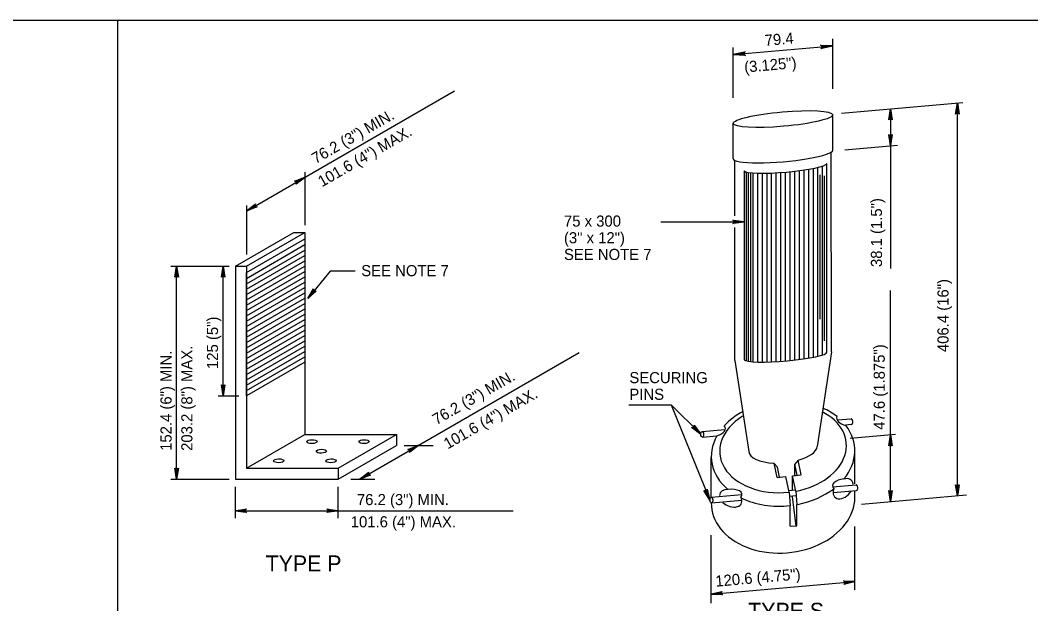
# Model space of a CAD drawing. Extents: x 640253 to 641999, y 298458 to 299646.
# Drawn here: x 640526.1 to 640798.8, y 298630.1 to 298787.7 of the extents above; entities that cross this region are included whole.
import ezdxf

# ---------------------------------------------------------------- set-up
doc = ezdxf.new("R2010")
doc.units = 0
doc.layers.add('1', color=7, linetype='Continuous')
doc.layers.add('2', color=7, linetype='Continuous')

msp = doc.modelspace()

# ---------------------------------------------------------------- linework, layer by layer
at = {"layer": '1'}
for p, q in [((640293.31, 298787.67), (641079.31, 298787.67)), ((640552.4, 298501.97), (640552.4, 298787.67))]:
    msp.add_line(p, q, dxfattribs=at)
at = {"layer": '2'}
for p, q in [((640745.35, 298769.11), (640745.35, 298782.64)), ((640718.51, 298778.37), (640745.35, 298780.72)), ((640718.51, 298766.76), (640718.51, 298780.28)), ((640587.19, 298736.22), (640643.29, 298768.61)), ((640747.71, 298762.61), (640780.48, 298765.48)), ((640778.98, 298659.27), (640778.98, 298765.33)), ((640760.93, 298763.77), (640760.93, 298753.8)), ((640745.35, 298752.61), (640745.35, 298762.15)), ((640718.51, 298750.3), (640718.51, 298759.84)), ((640744.97, 298698.11), (640744.96, 298752.08)), ((640748.58, 298752.71), (640762.8, 298753.96)), ((640760.93, 298753.8), (640760.93, 298720.65)), ((640718.9, 298734.89), (640718.9, 298749.84)), ((640743.77, 298698.07), (640743.76, 298748.98)), ((640602.93, 298732.38), (640602.93, 298746.61)), ((640721.41, 298746.98), (640721.41, 298696)), ((640721.41, 298746.59), (640721.63, 298746.81)), ((640722.06, 298695.59), (640722.06, 298746.56)), ((640722.61, 298695.59), (640722.61, 298746.55)), ((640723.24, 298695.59), (640723.24, 298746.56)), ((640723.86, 298695.45), (640723.86, 298746.43)), ((640725.11, 298695.4), (640725.11, 298746.37)), ((640726.36, 298695.39), (640726.36, 298746.36)), ((640727.61, 298695.4), (640727.61, 298746.38)), ((640728.86, 298695.45), (640728.86, 298746.42)), ((640730.11, 298695.51), (640730.11, 298746.48)), ((640731.36, 298695.59), (640731.36, 298746.57)), ((640732.61, 298695.69), (640732.61, 298746.66)), ((640733.86, 298695.81), (640733.86, 298746.78)), ((640735.11, 298695.94), (640735.11, 298746.91)), ((640736.36, 298696.1), (640736.36, 298747.07)), ((640737.61, 298696.27), (640737.61, 298747.24)), ((640738.86, 298696.47), (640738.86, 298747.44)), ((640740.11, 298696.7), (640740.11, 298747.67)), ((640741.36, 298696.98), (640741.36, 298747.95)), ((640742.61, 298697.33), (640742.61, 298748.3)), ((640743.76, 298748.51), (640743.55, 298748.73)), ((640741.93, 298706.99), (640741.93, 298745.92)), ((640743.12, 298701.13), (640743.12, 298745.69)), ((640587.19, 298724.38), (640587.19, 298737.68)), ((640698.95, 298733.24), (640721.41, 298733.24)), ((640584.12, 298721.28), (640599.86, 298730.37)), ((640587.12, 298721.28), (640602.86, 298730.37)), ((640599.86, 298730.37), (640602.86, 298730.37)), ((640602.86, 298730.37), (640602.86, 298675.87)), ((640718.91, 298695.83), (640718.9, 298731.67)), ((640587.12, 298717.99), (640602.86, 298727.08)), ((640587.12, 298716.54), (640602.86, 298725.63)), ((640587.12, 298715.1), (640602.86, 298724.19)), ((640587.12, 298713.66), (640602.86, 298722.75)), ((640566.74, 298721.28), (640582.49, 298721.28)), ((640568.28, 298663.78), (640568.28, 298721.28)), ((640580.82, 298686.28), (640580.82, 298721.28)), ((640584.12, 298721.28), (640587.12, 298721.28)), ((640584.12, 298721.28), (640584.12, 298663.78)), ((640587.12, 298712.21), (640602.86, 298721.3)), ((640587.12, 298721.28), (640587.12, 298666.78)), ((640587.12, 298710.77), (640602.86, 298719.86)), ((640587.12, 298719.28), (640587.35, 298719.68)), ((640587.12, 298719.32), (640587.32, 298719.66)), ((640609.71, 298719.96), (640603.7, 298712.54)), ((640616.48, 298719.96), (640609.71, 298719.96)), ((640587.12, 298709.33), (640602.86, 298718.41)), ((640587.12, 298707.88), (640602.86, 298716.97)), ((640587.12, 298706.44), (640602.86, 298715.53)), ((640587.12, 298705), (640602.86, 298714.09)), ((640760.93, 298657.71), (640760.93, 298714.7)), ((640587.12, 298703.55), (640602.86, 298712.64)), ((640587.12, 298702.11), (640602.86, 298711.2)), ((640587.12, 298700.67), (640602.86, 298709.75)), ((640587.12, 298699.22), (640602.86, 298708.31)), ((640587.12, 298697.78), (640602.86, 298706.87)), ((640587.12, 298696.34), (640602.86, 298705.43)), ((640587.12, 298694.89), (640602.86, 298703.98)), ((640587.12, 298693.45), (640602.86, 298702.54)), ((640587.12, 298692.01), (640602.86, 298701.09)), ((640587.12, 298690.56), (640602.86, 298699.65)), ((640587.12, 298689.12), (640602.86, 298698.21)), ((640617.72, 298663.78), (640676.89, 298697.94)), ((640744.97, 298698.11), (640741.18, 298672.58)), ((640587.12, 298687.68), (640602.86, 298696.76)), ((640718.91, 298695.83), (640722.69, 298671.24)), ((640579.47, 298686.28), (640585.04, 298686.28)), ((640690.3, 298683.85), (640701.76, 298683.85)), ((640701.76, 298683.85), (640709.73, 298675.91)), ((640701.76, 298683.85), (640712.18, 298658.13)), ((640746.61, 298679.77), (640750.3, 298680.09)), ((640748.75, 298678.44), (640750.42, 298678.58)), ((640587.12, 298666.78), (640602.86, 298675.87)), ((640602.86, 298675.87), (640627.58, 298675.87)), ((640611.84, 298666.78), (640627.58, 298675.87)), ((640627.58, 298675.87), (640627.58, 298672.87)), ((640710.07, 298676.65), (640716.25, 298677.17)), ((640710.18, 298675.14), (640714.07, 298675.47)), ((640750.09, 298674.81), (640762.33, 298675.88)), ((640611.84, 298663.78), (640627.58, 298672.87)), ((640629.69, 298672.87), (640637.47, 298672.87)), ((640751.32, 298662.52), (640751.32, 298671.49)), ((640712.57, 298658.9), (640712.57, 298669.6)), ((640730.36, 298664.26), (640729.56, 298668.13)), ((640729.58, 298668.02), (640730.45, 298667.02)), ((640736.01, 298668.88), (640735.1, 298667.79)), ((640735.1, 298664.75), (640735.1, 298667.79)), ((640735.72, 298664.82), (640735.1, 298667.79)), ((640736.83, 298664.91), (640736, 298668.9)), ((640587.12, 298666.78), (640611.84, 298666.78)), ((640611.84, 298666.78), (640611.84, 298663.78)), ((640730.36, 298664.26), (640732.68, 298664.47)), ((640731.01, 298664.3), (640730.45, 298667.02)), ((640733.56, 298660.25), (640732.68, 298664.47)), ((640734.51, 298664.7), (640736.83, 298664.91)), ((640735.37, 298660.56), (640734.51, 298664.7)), ((640734.51, 298660.92), (640734.51, 298664.7)), ((640566.74, 298663.78), (640582.49, 298663.78)), ((640584.12, 298663.78), (640611.84, 298663.78)), ((640584.12, 298653.23), (640584.12, 298661.74)), ((640611.84, 298653.23), (640611.84, 298661.74)), ((640615.31, 298663.78), (640621.72, 298663.78)), ((640745.28, 298661.72), (640751.64, 298662.26)), ((640712.51, 298658.91), (640720.85, 298659.63)), ((640733.46, 298660.71), (640735.31, 298660.86)), ((640733.56, 298660.25), (640733.88, 298656.62)), ((640733.65, 298659.21), (640735.48, 298659.36)), ((640735.5, 298651.22), (640734.51, 298659.03)), ((640735.37, 298660.56), (640735.7, 298656.93)), ((640745.44, 298660.21), (640751.77, 298660.75)), ((640751.32, 298658.55), (640751.32, 298660.75)), ((640753.15, 298657.03), (640781.49, 298659.51)), ((640712.63, 298657.41), (640720.84, 298658.11)), ((640733.88, 298651.05), (640733.88, 298656.62)), ((640735.7, 298651.21), (640735.7, 298656.93)), ((640584.12, 298655.27), (640659.11, 298655.27)), ((640733.88, 298651.05), (640735.7, 298651.21)), ((640751.32, 298633.93), (640751.32, 298651.02)), ((640712.57, 298630.28), (640712.57, 298648.65)), ((640712.57, 298632.73), (640751.32, 298636.12))]:
    msp.add_line(p, q, dxfattribs=at)
for points in [[(640721.62, 298778.25), (640721.48, 298778.47), (640718.51, 298778.37), (640721.62, 298778.25), (640721.78, 298778.13), (640718.51, 298778.37), (640721.45, 298778.78), (640721.54, 298779.01), (640718.51, 298778.37), (640721.69, 298779.17), (640721.54, 298779.01)], [(640721.62, 298778.25), (640721.48, 298778.47), (640718.51, 298778.37), (640721.62, 298778.25), (640721.78, 298778.13), (640718.51, 298778.37), (640721.45, 298778.78), (640721.54, 298779.01), (640718.51, 298778.37), (640721.69, 298779.17), (640721.54, 298779.01)], [(640742.24, 298780.84), (640742.38, 298780.63), (640745.35, 298780.72), (640742.24, 298780.84), (640742.07, 298780.96), (640745.35, 298780.72), (640742.41, 298780.32), (640742.32, 298780.09), (640745.35, 298780.72), (640742.17, 298779.92), (640742.32, 298780.09)], [(640778.62, 298762.47), (640778.83, 298762.58), (640778.98, 298765.33), (640778.62, 298762.47), (640778.5, 298762.33), (640778.98, 298765.33), (640779.12, 298762.58), (640779.32, 298762.48), (640778.98, 298765.33), (640779.46, 298762.33), (640779.32, 298762.48)], [(640760.57, 298760.91), (640760.78, 298761.02), (640760.93, 298763.77), (640760.57, 298760.91), (640760.45, 298760.77), (640760.93, 298763.77), (640761.06, 298761.02), (640761.27, 298760.92), (640760.93, 298763.77), (640761.41, 298760.77), (640761.27, 298760.92)], [(640761.29, 298756.65), (640761.08, 298756.54), (640760.93, 298753.8), (640761.29, 298756.65), (640761.41, 298756.8), (640760.93, 298753.8), (640760.79, 298756.54), (640760.59, 298756.64), (640760.93, 298753.8), (640760.45, 298756.8), (640760.59, 298756.64)], [(640600.28, 298744.19), (640600.48, 298744.07), (640602.93, 298745.31), (640600.28, 298744.19), (640600.09, 298744.23), (640602.93, 298745.31), (640600.62, 298743.82), (640600.64, 298743.59), (640602.93, 298745.31), (640600.57, 298743.39), (640600.64, 298743.59)], [(640589.84, 298737.33), (640589.64, 298737.46), (640587.19, 298736.22), (640589.84, 298737.33), (640590.03, 298737.3), (640587.19, 298736.22), (640589.5, 298737.71), (640589.48, 298737.93), (640587.19, 298736.22), (640589.55, 298738.13), (640589.48, 298737.93)], [(640718.56, 298733.6), (640718.66, 298733.39), (640721.41, 298733.24), (640718.56, 298733.6), (640718.41, 298733.72), (640721.41, 298733.24), (640718.66, 298733.11), (640718.56, 298732.9), (640721.41, 298733.24), (640718.41, 298732.76), (640718.56, 298732.9)], [(640567.92, 298718.43), (640568.13, 298718.53), (640568.28, 298721.28), (640567.92, 298718.43), (640567.8, 298718.28), (640568.28, 298721.28), (640568.42, 298718.53), (640568.62, 298718.43), (640568.28, 298721.28), (640568.76, 298718.28), (640568.62, 298718.43)], [(640580.46, 298718.43), (640580.67, 298718.53), (640580.82, 298721.28), (640580.46, 298718.43), (640580.34, 298718.28), (640580.82, 298721.28), (640580.96, 298718.53), (640581.16, 298718.43), (640580.82, 298721.28), (640581.3, 298718.28), (640581.16, 298718.43)], [(640605.78, 298714.53), (640605.55, 298714.58), (640603.7, 298712.54), (640605.78, 298714.53), (640605.97, 298714.56), (640603.7, 298712.54), (640605.33, 298714.75), (640605.23, 298714.96), (640603.7, 298712.54), (640605.22, 298715.17), (640605.23, 298714.96)], [(640581.18, 298689.13), (640580.97, 298689.03), (640580.82, 298686.28), (640581.18, 298689.13), (640581.3, 298689.28), (640580.82, 298686.28), (640580.69, 298689.03), (640580.48, 298689.13), (640580.82, 298686.28), (640580.34, 298689.28), (640580.48, 298689.13)], [(640707.95, 298678.17), (640707.88, 298677.95), (640709.73, 298675.91), (640707.95, 298678.17), (640707.93, 298678.36), (640709.73, 298675.91), (640707.68, 298677.74), (640707.47, 298677.67), (640709.73, 298675.91), (640707.26, 298677.68), (640707.47, 298677.67)], [(640760.57, 298672.9), (640760.78, 298673.01), (640760.93, 298675.75), (640760.57, 298672.9), (640760.45, 298672.75), (640760.93, 298675.75), (640761.06, 298673.01), (640761.27, 298672.91), (640760.93, 298675.75), (640761.41, 298672.75), (640761.27, 298672.91)], [(640630.82, 298671.76), (640631.02, 298671.63), (640633.47, 298672.87), (640630.82, 298671.76), (640630.63, 298671.79), (640633.47, 298672.87), (640631.16, 298671.38), (640631.18, 298671.16), (640633.47, 298672.87), (640631.11, 298670.96), (640631.18, 298671.16)], [(640568.64, 298666.63), (640568.43, 298666.53), (640568.28, 298663.78), (640568.64, 298666.63), (640568.76, 298666.78), (640568.28, 298663.78), (640568.14, 298666.53), (640567.94, 298666.63), (640568.28, 298663.78), (640567.8, 298666.78), (640567.94, 298666.63)], [(640620.37, 298664.9), (640620.18, 298665.02), (640617.72, 298663.78), (640620.37, 298664.9), (640620.56, 298664.86), (640617.72, 298663.78), (640620.03, 298665.27), (640620.02, 298665.5), (640617.72, 298663.78), (640620.08, 298665.69), (640620.02, 298665.5)], [(640779.34, 298662.13), (640779.13, 298662.02), (640778.98, 298659.27), (640779.34, 298662.13), (640779.46, 298662.27), (640778.98, 298659.27), (640778.85, 298662.02), (640778.64, 298662.12), (640778.98, 298659.27), (640778.5, 298662.27), (640778.64, 298662.12)], [(640711.42, 298660.91), (640711.27, 298660.73), (640712.18, 298658.13), (640711.42, 298660.91), (640711.48, 298661.09), (640712.18, 298658.13), (640711.01, 298660.62), (640710.78, 298660.64), (640712.18, 298658.13), (640710.59, 298660.73), (640710.78, 298660.64)], [(640761.29, 298660.57), (640761.08, 298660.46), (640760.93, 298657.71), (640761.29, 298660.57), (640761.41, 298660.71), (640760.93, 298657.71), (640760.79, 298660.46), (640760.59, 298660.56), (640760.93, 298657.71), (640760.45, 298660.71), (640760.59, 298660.56)], [(640586.97, 298654.91), (640586.87, 298655.12), (640584.12, 298655.27), (640586.97, 298654.91), (640587.12, 298654.79), (640584.12, 298655.27), (640586.87, 298655.41), (640586.97, 298655.61), (640584.12, 298655.27), (640587.12, 298655.75), (640586.97, 298655.61)], [(640608.98, 298655.63), (640609.09, 298655.42), (640611.84, 298655.27), (640608.98, 298655.63), (640608.84, 298655.75), (640611.84, 298655.27), (640609.09, 298655.14), (640608.99, 298654.93), (640611.84, 298655.27), (640608.84, 298654.79), (640608.99, 298654.93)], [(640748.44, 298636.23), (640748.57, 298636.03), (640751.32, 298636.12), (640748.44, 298636.23), (640748.29, 298636.34), (640751.32, 298636.12), (640748.6, 298635.75), (640748.51, 298635.53), (640751.32, 298636.12), (640748.37, 298635.38), (640748.51, 298635.53)], [(640715.45, 298632.62), (640715.32, 298632.82), (640712.57, 298632.73), (640715.45, 298632.62), (640715.6, 298632.51), (640712.57, 298632.73), (640715.29, 298633.1), (640715.37, 298633.32), (640712.57, 298632.73), (640715.52, 298633.47), (640715.37, 298633.32)]]:
    msp.add_lwpolyline(points, dxfattribs=at)
msp.add_lwpolyline([(640587.12, 298686.28), (640587.12, 298719.55), (640602.86, 298728.64), (640602.86, 298695.37)], close=True, dxfattribs=at)
for centre, major_axis, ratio in [((640731.93, 298760.98), (13.42, 1.17), 0.145281), ((640710.12, 298675.89), (0.064, -0.752), 0.512732), ((640604.79, 298673.91), (1.39, 0.03), 0.379302), ((640618.87, 298673.91), (1.39, 0.03), 0.379302), ((640607.35, 298671.32), (1.39, 0.03), 0.379302), ((640595.82, 298668.73), (1.39, 0.03), 0.379302), ((640609.91, 298668.73), (1.39, 0.03), 0.379302), ((640712.57, 298658.16), (0.064, -0.752), 0.512732)]:
    msp.add_ellipse(centre, major_axis=major_axis, ratio=ratio, dxfattribs=at)
for centre, major_axis, ratio, start_param, end_param in [((640731.93, 298751.43), (13.42, 1.17), 0.145281, 3.11632, 6.285895), ((640732.57, 298748.05), (11.2, 0.98), 0.122972, 3.210002, 6.25293), ((640732.58, 298697.08), (11.2, 0.98), 0.122972, 3.210002, 6.291685), ((640731.94, 298672.08), (17.07, 1.49), 0.694967, 2.202733, 4.738504), ((640731.94, 298670.7), (19.33, 1.69), 0.73071, 2.097917, 2.468804), ((640731.94, 298672.08), (17.07, 1.49), 0.694967, 4.864246, 7.131508), ((640731.94, 298670.7), (19.33, 1.69), 0.73071, 0.656059, 0.918196), ((640712.01, 298677.2), (-4.38, -0.28), 0.475219, 2.036448, 3.493745), ((640750.78, 298680.04), (4.38, -0.28), 0.475219, 2.977963, 4.296796), ((640731.94, 298670.7), (19.33, 1.69), 0.73071, 5.661526, 6.723992), ((640750.36, 298679.33), (0.064, -0.752), 0.512732, 0.00107, 3.141593), ((640731.94, 298670.7), (19.33, 1.69), 0.73071, 2.680187, 3.772289), ((640732.14, 298672.12), (9.04, 0.79), 0.424128, 5.116194, 6.19738), ((640731.73, 298672.03), (9.04, 0.79), 0.424128, 3.141593, 4.432781), ((640748.9, 298662.15), (3.65, 0.24), 0.475219, 1.675831, 3.574843), ((640748.15, 298661.2), (2.24, 2.27), 0.672987, 5.779184, 7.175378), ((640751.7, 298661.51), (0.064, -0.752), 0.512732, 0.00107, 3.141593), ((640717.83, 298658.61), (2.87, -1.38), 0.672987, 2.130551, 3.418187), ((640717.83, 298658.61), (2.87, -1.38), 0.672987, 4.245803, 7.059428), ((640717.22, 298659.25), (-3.62, -0.53), 0.475219, 2.692089, 4.679207), ((640731.94, 298670.7), (19.33, 1.69), 0.73071, 4.853626, 5.433989), ((640748.15, 298661.2), (2.24, 2.27), 0.672987, 2.176573, 5.044432), ((640731.94, 298658.04), (19.33, 1.69), 0.73071, 3.065603, 6.219513), ((640731.94, 298670.7), (19.33, 1.69), 0.73071, 4.023734, 4.749104)]:
    msp.add_ellipse(centre, major_axis=major_axis, ratio=ratio, start_param=start_param, end_param=end_param, dxfattribs=at)

# ---------------------------------------------------------------- texts
for s, rotation, p in [('79.4', 5.0068, (640727.12, 298780.7)), ('(3.125")', 5.0068, (640721.59, 298773.52)), ('76.2 (3") MIN.', 30, (640605.81, 298748.79)), ('101.6 (4") MAX.', 30, (640607.5, 298742.55)), ('38.1 (1.5")', 90, (640758.64, 298721.04)), ('406.4 (16")', 90, (640776.61, 298698.08)), ('125 (5")', 90, (640579.45, 298693.52)), ('47.6 (1.875")', 90, (640759.4, 298677.12)), ('152.4 (6") MIN.', 90, (640566.91, 298671.41)), ('203.2 (8") MAX.', 90, (640572.53, 298671.41)), ('76.2 (3") MIN.', 30, (640638.4, 298678.32)), ('101.6 (4") MAX.', 30, (640641.43, 298671.78)), ('120.6 (4.75")', 5.0052, (640713.8, 298634.73))]:
    msp.add_text(s, height=3, rotation=rotation, dxfattribs=at).set_placement(p)
for s, height, p in [('75 x 300', 3, (640672.81, 298731.95)), ('(3" x 12")', 3, (640672.81, 298727.45)), ('SEE NOTE 7', 3, (640672.81, 298722.95)), ('SEE NOTE 7', 3, (640618.1, 298718.57)), ('SECURING', 3, (640690.46, 298689.69)), ('PINS', 3, (640690.46, 298685.19)), ('76.2 (3") MIN.', 3, (640616.93, 298656.77)), ('101.6 (4") MAX.', 3, (640615.26, 298650.77)), ('TYPE P', 4.3, (640592.3, 298638.89)), ('TYPE S', 4.3, (640722.54, 298626.11))]:
    msp.add_text(s, height=height, dxfattribs=at).set_placement(p)

doc.saveas('drawing.dxf')
